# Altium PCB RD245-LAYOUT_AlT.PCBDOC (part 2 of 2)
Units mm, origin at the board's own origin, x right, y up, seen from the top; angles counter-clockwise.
Board outline 75 x 91 mm, 4 copper layers (TOP, Mid-Layer 1, Mid-Layer 2, BOTTOM), stack 0.711 mm thick; 95 components, 67 nets, 327 pads, 801 vias.
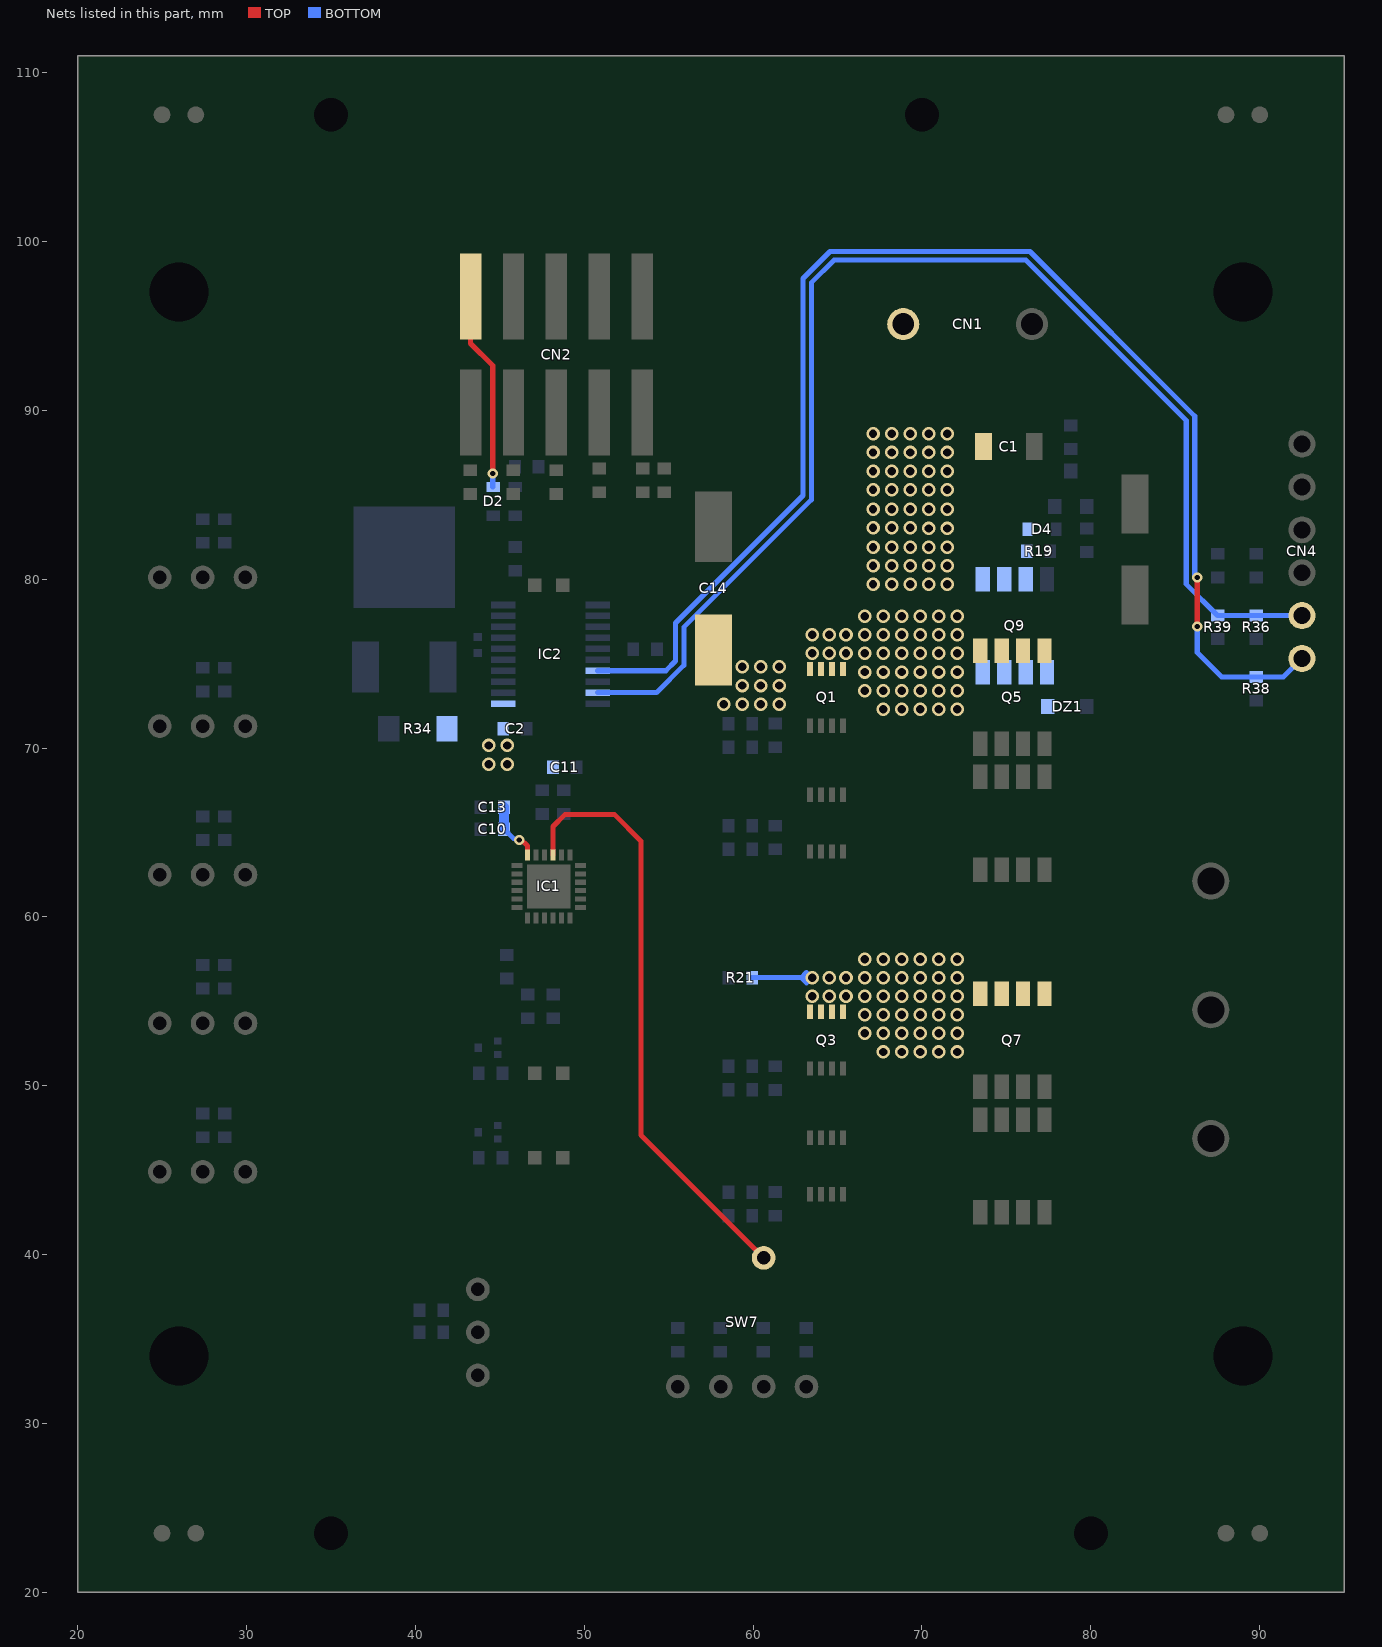
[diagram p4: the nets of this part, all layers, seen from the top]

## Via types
v1: diameter 0.8, hole 0.5, TOP to BOTTOM, 435 vias
v2: diameter 0.6, hole 0.3, TOP to BOTTOM, 356 vias
v3: diameter 0.5, hole 0.25, TOP to BOTTOM, 10 vias

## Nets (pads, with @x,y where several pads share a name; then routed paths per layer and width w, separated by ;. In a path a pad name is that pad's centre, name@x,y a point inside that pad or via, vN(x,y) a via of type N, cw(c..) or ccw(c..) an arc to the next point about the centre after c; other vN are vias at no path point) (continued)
SIG642: CN4.5 IC2.19 R36.1 R39.2 | length 75.6
  BOTTOM w0.3: IC2.19@50.8,73.275 54.275,73.275 55.9,74.9 55.9,77.15 63.45,84.7 63.45,97.55 64.8,98.9 76.15,98.9 85.65,89.4 85.65,79.7 R39.2@87.5,77.85 R36.1@89.8,77.85 89.81,77.84 CN4.5@92.5,77.84
SIG643: CN4.6 IC2.17 R38.2 | length 80
  TOP w0.3: v2(86.3,77.2) v2(86.3,80.1)
  BOTTOM w0.3: IC2.17@50.8,74.575 54.825,74.575 55.4,75.15 55.4,77.4 62.95,84.95 62.95,97.8 64.55,99.4 76.4,99.4 86.15,89.65 86.15,80.4 ; v2@86.15,80.25 86.15,80.4 ; v2(86.3,77.2) 86.3,75.65 87.75,74.2 R38.2@89.8,74.2 91.4,74.2 CN4.6@92.5,75.3 ; v2(86.3,80.1) 86.15,80.4
VB: C2.2 C10.2 C11.2 C13.2 C14.2 DZ1.C IC1.18 IC2.1 Q1.5 Q1.6 Q1.7 Q1.8 Q3.5 Q3.6 Q3.7 Q3.8 Q5.5 Q5.6 Q5.7 Q5.8 Q7.5 Q7.6 Q7.7 Q7.8 Q9.5 Q9.6 Q9.7 Q9.8 R21.1 R34.1 | length 8
  TOP w0.3: v2(46.15,64.55) 46.5,64.35 46.65,64.2 IC1.18@46.65,63.675
  BOTTOM w0.3: C10.2@45.25,65.2 45.8,64.65 v2(46.15,64.55) ; R21.1@59.95,56.4 62.85,56.4 ; 63.15,56.1 62.85,56.4 ; 63.15,56.7 62.85,56.4 ; v1(63.5,56.4) 62.85,56.4
  BOTTOM w0.6: C10.2@45.25,65.2 C13.2@45.25,66.5
  other v1: 67.7,52 68.8,52 69.9,52 71,52 72.1,52 66.6,53.1 67.7,53.1 68.8,53.1 69.9,53.1 71,53.1 72.1,53.1 66.6,54.2 67.7,54.2 68.8,54.2 69.9,54.2 71,54.2 72.1,54.2 63.5,55.3 64.5,55.3 65.5,55.3 66.6,55.3 67.7,55.3 68.8,55.3 69.9,55.3 71,55.3 72.1,55.3 64.5,56.4 65.5,56.4 66.6,56.4 67.7,56.4 68.8,56.4 69.9,56.4 71,56.4 72.1,56.4 66.6,57.5 67.7,57.5 68.8,57.5 69.9,57.5 71,57.5 72.1,57.5 44.35,69.05 45.45,69.05 44.35,70.15 45.45,70.15 67.7,72.3 68.8,72.3 69.9,72.3 71,72.3 72.1,72.3 58.25,72.6 59.35,72.6 60.45,72.6 61.55,72.6 66.6,73.4 67.7,73.4 68.8,73.4 69.9,73.4 71,73.4 72.1,73.4 59.35,73.7 60.45,73.7 61.55,73.7 66.6,74.5 67.7,74.5 68.8,74.5 69.9,74.5 71,74.5 72.1,74.5 59.35,74.8 60.45,74.8 61.55,74.8 63.5,75.6 64.5,75.6 65.5,75.6 66.6,75.6 67.7,75.6 68.8,75.6 69.9,75.6 71,75.6 72.1,75.6 63.5,76.7 64.5,76.7 65.5,76.7 66.6,76.7 67.7,76.7 68.8,76.7 69.9,76.7 71,76.7 72.1,76.7 66.6,77.8 67.7,77.8 68.8,77.8 69.9,77.8 71,77.8 72.1,77.8
VBAT: C1.1 CN1.1 D4.K Q9.1 Q9.2 Q9.3 R19.1
  other v1: 67.1,79.7 68.2,79.7 69.3,79.7 70.4,79.7 71.5,79.7 67.1,80.8 68.2,80.8 69.3,80.8 70.4,80.8 71.5,80.8 67.1,81.9 68.2,81.9 69.3,81.9 70.4,81.9 71.5,81.9 70.4,83 71.5,83 67.1,83.05 68.2,83.05 69.3,83.05 67.1,84.15 68.2,84.15 69.3,84.15 70.4,84.15 71.5,84.15 67.1,85.3 68.2,85.3 69.3,85.3 70.4,85.3 71.5,85.3 67.1,86.4 68.2,86.4 69.3,86.4 70.4,86.4 71.5,86.4 67.1,87.5 68.2,87.5 69.3,87.5 70.4,87.5 71.5,87.5 67.1,88.6 68.2,88.6 69.3,88.6 70.4,88.6 71.5,88.6
VDS: IC1.15 SW7.C | length 35.5
  TOP w0.3: IC1.15@48.15,63.675 48.15,65.35 48.85,66.05 51.8,66.05 53.35,64.5 53.35,47.08 SW7.C@60.62,39.81
VEXT: CN2.2 D2.A | length 11.8
  TOP w0.3: CN2.2@43.27,96.729 43.27,93.96 44.58,92.65 v2(44.58,86.25)
  BOTTOM w0.3: v2(44.58,86.25) 44.58,85.47 D2.A@44.6,85.45
pads on no net: IC2.4 IC2.6 IC2.9 IC2.12 IC2.18

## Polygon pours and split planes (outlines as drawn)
no net on TOP "TOP3" (solid, pour order 52): 21,105 21,110 94,110 94,105
no net on TOP "TOP4" (solid, pour order 53): 21,21 21,26 94,26 94,21
VBAT on TOP "TOP1" (solid, pour order 50): 64.9,79.775 64.9,96.879 cw(c64.95,96.879) 64.915,96.915 65.385,97.385 cw(c65.421,97.35) 65.421,97.4 74.379,97.4 cw(c74.379,97.35) 74.415,97.385 74.885,96.915 cw(c74.85,96.879) 74.9,96.879 74.9,79.775 74.4,79.275 65.4,79.275
VB on TOP "TOP7" (solid, pour order 56): 66.846,71.675 cw(c66.846,71.725) 66.81,71.69 66.25,72.25 62.1,72.25 cw(c62.1,72.3) 62.05,72.3 62.05,78.525 cw(c62.1,78.525) 62.1,78.575 77.159,78.575 cw(c77.159,78.525) 77.195,78.56 77.665,78.09 cw(c77.63,78.054) 77.68,78.054 77.68,71.725 cw(c77.63,71.725) 77.63,71.675
GND on TOP "TOP8" (solid, pour order 57): 63.646,58.55 cw(c63.646,58.6) 63.61,58.565 63.115,59.06 cw(c63.15,59.096) 63.1,59.096 63.1,64.25 cw(c63.15,64.25) 63.15,64.3 64.875,64.3 cw(c64.875,64.25) 64.925,64.25 64.925,63.55 ccw(c65.225,63.55) 65.225,63.25 66.425,63.25 66.685,63.51 cw(c66.721,63.475) 66.721,63.525 67.209,63.525 67.21,63.525 76.36,63.525 cw(c76.36,63.475) 76.41,63.475 76.41,59.071 cw(c76.36,59.071) 76.395,59.035 75.925,58.565 cw(c75.889,58.6) 75.889,58.55
VB on TOP "TOP9" (solid, pour order 58): 66.771,51.375 cw(c66.771,51.425) 66.735,51.39 66.175,51.95 62.1,51.95 cw(c62.1,52) 62.05,52 62.05,58 cw(c62.1,58) 62.1,58.05 77.159,58.05 cw(c77.159,58) 77.195,58.035 77.665,57.565 cw(c77.63,57.529) 77.68,57.529 77.68,51.425 cw(c77.63,51.425) 77.63,51.375
OUT1 on TOP "TOP11" (solid, pour order 60): 79.321,58.55 cw(c79.321,58.6) 79.285,58.565 78.815,59.035 cw(c78.85,59.071) 78.8,59.071 78.8,63.1 77.675,64.225 66.796,64.225 cw(c66.796,64.275) 66.76,64.24 66.2,64.8 63.1,64.8 cw(c63.1,64.85) 63.05,64.85 63.05,71.7 cw(c63.1,71.7) 63.1,71.75 64.875,71.75 cw(c64.875,71.7) 64.925,71.7 64.925,71 ccw(c65.225,71) 65.225,70.7 66.4,70.7 66.66,70.96 cw(c66.696,70.925) 66.696,70.975 76.36,70.975 cw(c76.36,70.925) 76.41,70.925 76.41,69.525 ccw(c76.71,69.525) 76.71,69.225 77.655,69.225 ccw(c77.655,69.55) 77.98,69.55 77.98,69.6 cw(c78.03,69.6) 78.03,69.65 78.2,69.65 ccw(c78.2,70.25) 78.8,70.25 78.8,70.779 cw(c78.85,70.779) 78.815,70.815 78.985,70.985 cw(c79.021,70.95) 79.021,71 80.329,71 cw(c80.329,70.95) 80.365,70.985 86,65.35 90.479,65.35 cw(c90.479,65.3) 90.515,65.335 90.985,64.865 cw(c90.95,64.829) 91,64.829 91,59.071 cw(c90.95,59.071) 90.985,59.035 90.515,58.565 cw(c90.479,58.6) 90.479,58.55
OUT2 on TOP "TOP12" (solid, pour order 61): 79.601,43.925 66.796,43.925 cw(c66.796,43.975) 66.76,43.94 66.2,44.5 63.1,44.5 cw(c63.1,44.55) 63.05,44.55 63.05,51.4 cw(c63.1,51.4) 63.1,51.45 64.875,51.45 cw(c64.875,51.4) 64.925,51.4 64.925,50.7 ccw(c65.225,50.7) 65.225,50.4 66.35,50.4 66.61,50.66 cw(c66.646,50.625) 66.646,50.675 76.36,50.675 cw(c76.36,50.625) 76.41,50.625 76.41,49.225 ccw(c76.71,49.225) 76.71,48.925 77.655,48.925 ccw(c77.655,49.25) 77.98,49.25 77.98,49.259 cw(c78.03,49.259) 77.995,49.295 78.035,49.335 cw(c78.071,49.3) 78.071,49.35 78.2,49.35 ccw(c78.2,49.95) 78.8,49.95 78.8,57.529 cw(c78.85,57.529) 78.815,57.565 79.285,58.035 cw(c79.321,58) 79.321,58.05 90.479,58.05 cw(c90.479,58) 90.515,58.035 90.985,57.565 cw(c90.95,57.529) 91,57.529 91,51.771 cw(c90.95,51.771) 90.985,51.735 90.515,51.265 cw(c90.479,51.3) 90.479,51.25 86.85,51.25 85.4,49.8 85.4,46.671 cw(c85.35,46.671) 85.385,46.635 82.69,43.94 cw(c82.654,43.975) 82.654,43.925
N622087 on TOP "TOP5" (solid, pour order 54): 81.85,84.8 cw(c81.85,84.85) 81.8,84.85 81.8,86.35 81.676,86.474 81.615,86.535 cw(c81.65,86.571) 81.6,86.571 81.6,87.929 cw(c81.65,87.929) 81.615,87.965 81.835,88.185 81.836,88.186 82.835,89.185 cw(c82.871,89.15) 82.871,89.2 93.029,89.2 cw(c93.029,89.15) 93.065,89.185 93.285,88.965 cw(c93.25,88.929) 93.3,88.929 93.3,87.471 cw(c93.25,87.471) 93.285,87.435 93.065,87.215 cw(c93.029,87.25) 93.029,87.2 84.25,87.2 83.586,86.536 83.585,86.535 83.4,86.35 83.4,84.85 cw(c83.35,84.85) 83.35,84.8
GND on TOP "TOP2" (solid, pour order 51): 43.571,57.6 cw(c43.571,57.65) 43.535,57.615 39.765,61.385 cw(c39.8,61.421) 39.75,61.421 39.75,61.629 cw(c39.8,61.629) 39.765,61.665 39.935,61.835 cw(c39.971,61.8) 39.971,61.85 40.184,61.85 cw(c40.184,61.8) 40.22,61.835 41.34,60.715 cw(c41.304,60.68) 41.351,60.697 41.43,60.48 41.43,60.479 41.43,60.478 ccw(c41.9,60.65) 41.9,60.15 42.834,60.15 cw(c42.834,60.1) 42.87,60.135 43.503,59.503 ccw(c43.75,59.75) 43.75,59.4 43.76,59.4 cw(c43.76,59.35) 43.781,59.395 43.985,59.299 43.985,59.298 ccw(c44.2,59.75) 44.531,59.375 44.83,59.636 44.833,59.639 45.283,60.038 ccw(c45.05,60.3) 45.297,60.052 45.298,60.053 45.299,60.054 45.43,60.185 cw(c45.466,60.15) 45.443,60.195 cw(c45.466,60.15) 45.466,60.2 46.079,60.2 cw(c46.079,60.15) 46.115,60.185 46.285,60.015 cw(c46.25,59.979) 46.3,59.979 46.3,59.607 cw(c46.25,59.607) 46.262,59.558 cw(c46.25,59.607) 46.257,59.557 46.179,59.545 46.178,59.545 ccw(c46.25,59.05) 46.256,58.55 46.257,58.55 46.279,58.55 cw(c46.279,58.5) 46.315,58.535 46.485,58.365 cw(c46.45,58.329) 46.5,58.329 46.5,57.771 cw(c46.45,57.771) 46.485,57.735 46.365,57.615 cw(c46.329,57.65) 46.352,57.605 cw(c46.329,57.65) 46.329,57.6
GND on TOP "TOP6" (solid, pour order 55): 43.566,60.45 cw(c43.566,60.5) 43.543,60.455 cw(c43.566,60.5) 43.53,60.465 39.765,64.23 cw(c39.8,64.266) 39.75,64.266 39.75,72.534 cw(c39.8,72.534) 39.765,72.57 43.48,76.285 cw(c43.516,76.25) 43.493,76.295 cw(c43.516,76.25) 43.516,76.3 49.2,76.3 ccw(c49.2,76.65) 49.447,76.403 51.047,78.003 ccw(c50.8,78.25) 51.15,78.25 51.15,82.334 cw(c51.2,82.334) 51.165,82.37 52.13,83.335 cw(c52.166,83.3) 52.166,83.35 52.479,83.35 cw(c52.479,83.3) 52.515,83.335 52.585,83.265 cw(c52.55,83.229) 52.6,83.229 52.6,72.166 cw(c52.55,72.166) 52.585,72.13 46.615,66.16 cw(c46.58,66.196) 46.596,66.149 46.38,66.07 46.376,66.069 ccw(c46.55,65.6) 46.05,65.6 46.05,65.079 cw(c46,65.079) 46.044,65.055 cw(c46,65.079) 46.014,65.031 ccw(c46.15,64.55) 45.65,64.55 ccw(c46.15,64.55) 46.078,64.055 46.079,64.055 46.081,64.055 46.257,64.03 cw(c46.25,63.981) 46.3,63.981 46.3,63.621 cw(c46.25,63.621) 46.297,63.603 cw(c46.25,63.621) 46.285,63.585 46.115,63.415 cw(c46.079,63.45) 46.093,63.402 cw(c46.079,63.45) 46.079,63.4 45.466,63.4 cw(c45.466,63.45) 45.45,63.403 cw(c45.466,63.45) 45.43,63.415 45.061,63.784 cw(c45.096,63.82) 45.049,63.803 44.97,64.02 44.97,64.021 44.969,64.024 44.968,64.025 ccw(c44.5,63.85) 44.325,63.381 44.327,63.381 44.329,63.38 44.33,63.38 44.331,63.38 44.331,63.379 44.547,63.301 cw(c44.53,63.254) 44.566,63.29 44.566,63.289 45.052,62.803 45.053,62.802 ccw(c45.3,63.05) 45.3,62.7 45.85,62.7 cw(c45.85,62.65) 45.9,62.65 45.9,62.45 cw(c45.85,62.45) 45.85,62.4 45.033,62.4 cw(c45.033,62.45) 45.003,62.41 44.983,62.425 cw(c45.012,62.466) 44.968,62.443 44.846,62.676 44.845,62.678 ccw(c44.4,62.45) 43.9,62.444 43.9,62.443 43.9,60.5 cw(c43.85,60.5) 43.85,60.45
VB on TOP "TOP10" (solid, pour order 59): 59.321,51.95 cw(c59.321,52) 59.285,51.965 55.265,55.985 cw(c55.3,56.021) 55.25,56.021 55.25,76.779 cw(c55.3,76.779) 55.265,76.815 57.01,78.56 cw(c57.046,78.525) 57.046,78.575 63.45,78.575 cw(c63.45,78.525) 63.5,78.525 63.5,72.3 cw(c63.45,72.3) 63.45,72.25 62.5,72.25 61.95,71.7 61.95,66.245 cw(c61.9,66.245) 61.918,66.199 61.917,66.198 ccw(c62.2,65.45) 61.918,64.701 cw(c61.9,64.655) 61.95,64.655 61.95,58.75 62.65,58.05 63.3,58.05 cw(c63.3,58) 63.35,58 63.35,52 cw(c63.3,52) 63.3,51.95
GND on TOP "TOP13" (solid, pour order 62): 39.671,74.45 cw(c39.671,74.5) 39.635,74.465 39.565,74.535 cw(c39.6,74.571) 39.55,74.571 39.55,75.434 cw(c39.6,75.434) 39.565,75.47 44.48,80.385 cw(c44.516,80.35) 44.516,80.4 46.65,80.4 ccw(c46.65,80.75) 46.897,80.503 49.48,83.085 cw(c49.516,83.05) 49.516,83.1 49.85,83.1 49.95,83 49.95,78.666 cw(c49.9,78.666) 49.935,78.63 48.82,77.515 cw(c48.784,77.55) 48.807,77.505 cw(c48.784,77.55) 48.784,77.5 43.05,77.5 ccw(c43.05,77.15) 42.803,77.397 42.554,77.149 42.553,77.148 39.87,74.465 cw(c39.834,74.5) 39.834,74.45
GND on TOP "TOP14" (solid, pour order 63): 31.521,29 cw(c31.521,29.05) 31.498,29.005 cw(c31.521,29.05) 31.485,29.015 31.015,29.485 cw(c31.05,29.521) 31.002,29.507 cw(c31.05,29.521) 31,29.521 31,34 ccw(c26,34) 26,39 21.521,39 cw(c21.521,39.05) 21.498,39.005 cw(c21.521,39.05) 21.485,39.015 21.015,39.485 cw(c21.05,39.521) 21.002,39.507 cw(c21.05,39.521) 21,39.521 21,91.479 cw(c21.05,91.479) 21.001,91.491 cw(c21.05,91.479) 21.015,91.515 21.016,91.516 21.485,91.985 cw(c21.521,91.95) 21.507,91.998 cw(c21.521,91.95) 21.521,92 26,92 ccw(c26,97) 31,97 31,101.479 cw(c31.05,101.479) 31.001,101.491 cw(c31.05,101.479) 31.015,101.515 31.016,101.516 31.485,101.985 cw(c31.521,101.95) 31.507,101.998 cw(c31.521,101.95) 31.521,102 83.479,102 cw(c83.479,101.95) 83.502,101.995 cw(c83.479,101.95) 83.515,101.985 83.517,101.983 83.518,101.982 83.984,101.516 83.985,101.515 cw(c83.95,101.479) 84,101.479 84,97 ccw(c89,97) 89,92 93.479,92 cw(c93.479,91.95) 93.502,91.995 cw(c93.479,91.95) 93.515,91.985 93.517,91.983 93.518,91.982 93.984,91.516 93.985,91.515 cw(c93.95,91.479) 94,91.479 94,39.521 cw(c93.95,39.521) 93.999,39.508 cw(c93.95,39.521) 93.985,39.485 93.984,39.484 93.515,39.015 cw(c93.479,39.05) 93.493,39.002 cw(c93.479,39.05) 93.479,39 89.051,39 89.05,39 ccw(c89,34) 84,34 84,29.521 cw(c83.95,29.521) 83.998,29.509 cw(c83.95,29.521) 83.985,29.485 83.984,29.484 83.515,29.015 cw(c83.479,29.05) 83.493,29.002 cw(c83.479,29.05) 83.479,29
GND on Mid-Layer 1 "MID122" (solid, pour order 49): 22,29 cw(c22,30) 21,30 21,101 cw(c22,101) 22,102 93,102 cw(c93,101) 94,101 94,30 cw(c93,30) 93,29
no net on Mid-Layer 1 "MID117" (solid, pour order 44): 21,105 21,110 94,110 94,105
no net on Mid-Layer 1 "MID118" (solid, pour order 45): 21,21 21,26 94,26 94,21
VB on Mid-Layer 1 "MID115" (solid, pour order 42): 66.771,51.375 cw(c66.771,51.425) 66.735,51.39 66.125,52 62.1,52 cw(c62.1,52.05) 62.05,52.05 62.05,58 cw(c62.1,58) 62.1,58.05 72.229,58.05 cw(c72.229,58) 72.265,58.035 72.735,57.565 cw(c72.7,57.529) 72.748,57.543 cw(c72.7,57.529) 72.75,57.529 72.75,51.896 cw(c72.7,51.896) 72.735,51.86 72.265,51.39 cw(c72.229,51.425) 72.243,51.377 cw(c72.229,51.425) 72.229,51.375
VB on Mid-Layer 1 "MID116" (solid, pour order 43): 66.771,71.675 cw(c66.771,71.725) 66.735,71.69 66.125,72.3 62.1,72.3 cw(c62.1,72.35) 62.05,72.35 62.05,78.525 cw(c62.1,78.525) 62.1,78.575 72.25,78.575 72.75,78.075 72.75,72.196 cw(c72.7,72.196) 72.735,72.16 72.265,71.69 cw(c72.229,71.725) 72.243,71.677 cw(c72.229,71.725) 72.229,71.675
VB on Mid-Layer 1 "MID119" (solid, pour order 46): 59.271,52 cw(c59.271,52.05) 59.235,52.015 55.265,55.985 cw(c55.3,56.021) 55.25,56.021 55.25,75.729 cw(c55.3,75.729) 55.265,75.765 58.06,78.56 cw(c58.096,78.525) 58.096,78.575 63.45,78.575 cw(c63.45,78.525) 63.5,78.525 63.5,72.35 cw(c63.45,72.35) 63.45,72.3 62.55,72.3 61.95,71.7 61.95,66.352 cw(c61.9,66.352) 61.935,66.317 61.634,66.016 ccw(c62.2,65.45) 61.634,64.884 61.935,64.583 cw(c61.9,64.548) 61.95,64.548 61.95,58.75 62.65,58.05 63.3,58.05 cw(c63.3,58) 63.35,58 63.35,52.05 cw(c63.3,52.05) 63.3,52
N622087 on Mid-Layer 1 "MID120" (solid, pour order 47): 81.6,86.45 81.6,87.95 81.85,88.2 83.35,88.2 83.6,87.95 83.6,86.45 83.35,86.2 81.85,86.2
N622087 on Mid-Layer 1 "MID121" (solid, pour order 48): 58.8,88.2 58.8,89.7 59.05,89.95 60.55,89.95 60.8,89.7 60.8,88.2 60.55,87.95 59.05,87.95
GND on Mid-Layer 2 "MID233" (solid, pour order 41): 22,29 cw(c22,30) 21,30 21,101 cw(c22,101) 22,102 93,102 cw(c93,101) 94,101 94,30 cw(c93,30) 93,29
no net on Mid-Layer 2 "MID226" (solid, pour order 34): 21,105 21,110 94,110 94,105
no net on Mid-Layer 2 "MID227" (solid, pour order 35): 21,21 21,26 94,26 94,21
VB on Mid-Layer 2 "MID223" (solid, pour order 31): 66.771,51.375 cw(c66.771,51.425) 66.735,51.39 66.125,52 62.1,52 cw(c62.1,52.05) 62.05,52.05 62.05,58 cw(c62.1,58) 62.1,58.05 72.229,58.05 cw(c72.229,58) 72.265,58.035 72.735,57.565 cw(c72.7,57.529) 72.748,57.543 cw(c72.7,57.529) 72.75,57.529 72.75,51.896 cw(c72.7,51.896) 72.735,51.86 72.265,51.39 cw(c72.229,51.425) 72.243,51.377 cw(c72.229,51.425) 72.229,51.375
VB on Mid-Layer 2 "MID224" (solid, pour order 32): 66.771,71.675 cw(c66.771,71.725) 66.735,71.69 66.125,72.3 62.1,72.3 cw(c62.1,72.35) 62.05,72.35 62.05,78.525 cw(c62.1,78.525) 62.1,78.575 72.25,78.575 72.75,78.075 72.75,72.196 cw(c72.7,72.196) 72.735,72.16 72.265,71.69 cw(c72.229,71.725) 72.243,71.677 cw(c72.229,71.725) 72.229,71.675
VBAT on Mid-Layer 2 "MID225" (solid, pour order 33): 64.9,79.775 64.9,96.879 cw(c64.95,96.879) 64.915,96.915 65.385,97.385 cw(c65.421,97.35) 65.421,97.4 74.379,97.4 cw(c74.379,97.35) 74.415,97.385 74.885,96.915 cw(c74.85,96.879) 74.9,96.879 74.9,79.775 74.4,79.275 65.4,79.275
VB on Mid-Layer 2 "MID228" (solid, pour order 36): 59.271,52 cw(c59.271,52.05) 59.235,52.015 55.265,55.985 cw(c55.3,56.021) 55.25,56.021 55.25,75.729 cw(c55.3,75.729) 55.265,75.765 58.06,78.56 cw(c58.096,78.525) 58.096,78.575 63.45,78.575 cw(c63.45,78.525) 63.5,78.525 63.5,72.35 cw(c63.45,72.35) 63.45,72.3 62.55,72.3 61.95,71.7 61.95,66.245 cw(c61.9,66.245) 61.918,66.199 ccw(c62.2,65.45) 61.918,64.701 cw(c61.9,64.655) 61.95,64.655 61.95,58.75 62.65,58.05 63.3,58.05 cw(c63.3,58) 63.35,58 63.35,52.05 cw(c63.3,52.05) 63.3,52
VB on Mid-Layer 2 "MID229" (solid, pour order 37): 55.521,67.85 cw(c55.521,67.9) 55.485,67.865 54.75,68.6 44.171,68.6 cw(c44.171,68.65) 44.135,68.615 43.915,68.835 cw(c43.95,68.871) 43.9,68.871 43.9,70.329 cw(c43.95,70.329) 43.915,70.365 44.135,70.585 cw(c44.171,70.55) 44.171,70.6 54.75,70.6 55.385,71.235 cw(c55.421,71.2) 55.421,71.25 55.85,71.25 cw(c55.85,71.2) 55.9,71.2 55.9,67.9 cw(c55.85,67.9) 55.85,67.85
OUT2 on Mid-Layer 2 "MID230" (solid, pour order 38): 79.601,43.925 66.796,43.925 cw(c66.796,43.975) 66.76,43.94 66.15,44.55 63.546,44.55 cw(c63.546,44.6) 63.51,44.565 63.04,45.035 cw(c63.075,45.071) 63.025,45.071 63.025,50.179 cw(c63.075,50.179) 63.04,50.215 63.51,50.685 cw(c63.546,50.65) 63.546,50.7 65.663,50.7 ccw(c66.15,51.05) 66.618,50.675 72.75,50.675 73.25,51.175 73.25,57.55 73.75,58.05 90.5,58.05 91,57.55 91,51.771 cw(c90.95,51.771) 90.985,51.735 90.515,51.265 cw(c90.479,51.3) 90.479,51.25 86.85,51.25 85.4,49.8 85.4,46.671 cw(c85.35,46.671) 85.385,46.635 82.69,43.94 cw(c82.654,43.975) 82.654,43.925
GND on Mid-Layer 2 "MID231" (solid, pour order 39): 63.625,58.55 63.125,59.05 63.125,63.025 63.625,63.525 65.682,63.525 ccw(c66.15,63.9) 66.618,63.525 75.91,63.525 76.41,63.025 76.41,59.05 75.91,58.55
OUT1 on Mid-Layer 2 "MID232" (solid, pour order 40): 77.431,58.55 cw(c77.431,58.6) 77.395,58.565 76.925,59.035 cw(c76.96,59.071) 76.91,59.071 76.91,63.725 76.41,64.225 66.796,64.225 cw(c66.796,64.275) 66.76,64.24 66.15,64.85 63.546,64.85 cw(c63.546,64.9) 63.51,64.865 63.04,65.335 cw(c63.075,65.371) 63.025,65.371 63.025,70.454 cw(c63.075,70.454) 63.04,70.49 63.51,70.96 cw(c63.546,70.925) 63.546,70.975 65.732,70.975 ccw(c66.2,71.35) 66.668,70.975 80.354,70.975 cw(c80.354,70.925) 80.39,70.96 86,65.35 90.5,65.35 91,64.85 91,59.071 cw(c90.95,59.071) 90.985,59.035 90.515,58.565 cw(c90.479,58.6) 90.479,58.55
GND on BOTTOM "BOTTOM62" (solid, pour order 30): 50.121,65 cw(c50.121,65.05) 50.085,65.015 49.915,65.185 cw(c49.95,65.221) 49.902,65.207 cw(c49.95,65.221) 49.9,65.221 49.9,68.21 cw(c49.95,68.21) 49.901,68.22 cw(c49.95,68.21) 49.92,68.25 cw(c49.95,68.21) 49.936,68.259 ccw(c49.875,68.475) 50.048,68.331 cw(c50.087,68.3) 50.059,68.342 cw(c50.087,68.3) 50.075,68.348 cw(c50.087,68.3) 50.087,68.35 52.05,68.35 ccw(c52.05,68.85) 52.404,68.496 57.504,73.596 ccw(c57.15,73.95) 57.65,73.95 57.65,76.372 cw(c57.7,76.372) 57.665,76.408 65.254,83.996 ccw(c64.9,84.35) 65.4,84.35 65.4,89.172 cw(c65.45,89.172) 65.401,89.184 cw(c65.45,89.172) 65.415,89.208 65.416,89.209 66.692,90.485 cw(c66.728,90.45) 66.714,90.498 cw(c66.728,90.45) 66.728,90.5 76.672,90.5 cw(c76.672,90.45) 76.695,90.495 cw(c76.672,90.45) 76.708,90.485 78.185,89.008 cw(c78.15,88.972) 78.2,88.972 78.2,85.975 ccw(c78.425,85.975) 78.425,85.75 79.175,85.75 ccw(c79.175,85.975) 79.4,85.975 79.4,86 cw(c79.45,86) 79.45,86.05 79.884,86.05 cw(c79.884,86) 79.907,86.045 cw(c79.884,86) 79.92,86.035 80.634,85.321 80.635,85.32 cw(c80.6,85.284) 80.65,85.284 80.65,80.716 cw(c80.6,80.716) 80.649,80.704 cw(c80.6,80.716) 80.635,80.68 80.634,80.679 80.32,80.365 cw(c80.284,80.4) 80.298,80.352 cw(c80.284,80.4) 80.284,80.35 78.351,80.35 cw(c78.351,80.4) 78.315,80.365 78.145,80.535 cw(c78.18,80.571) 78.132,80.557 cw(c78.18,80.571) 78.13,80.571 78.13,81 cw(c78.18,81) 78.135,81.022 cw(c78.18,81) 78.147,81.037 ccw(c77.925,81.275) 78.25,81.275 78.25,82.025 78.25,82.208 cw(c78.3,82.208) 78.288,82.256 78.29,82.257 ccw(c78.225,82.575) 78.55,82.575 78.55,84.725 ccw(c78.225,84.725) 78.225,85.05 77.271,85.05 cw(c77.271,85.1) 77.235,85.065 77.065,85.235 cw(c77.1,85.271) 77.052,85.257 cw(c77.1,85.271) 77.05,85.271 77.05,88.579 ccw(c76.5,88.579) 76.889,88.968 76.418,89.439 ccw(c76.029,89.05) 76.029,89.6 67.021,89.6 ccw(c67.021,89.05) 66.632,89.439 66.161,88.968 ccw(c66.55,88.579) 66,88.579 66,79.621 cw(c65.95,79.621) 65.999,79.609 cw(c65.95,79.621) 65.985,79.585 65.984,79.584 65.516,79.116 65.515,79.115 cw(c65.479,79.15) 65.479,79.1 61.021,79.1 ccw(c61.021,78.85) 60.844,79.027 60.843,79.026 60.82,79.003 60.819,79.002 cw(c60.784,79.038) 60.809,78.995 ccw(c61.096,78.525) 60.707,78.914 58.211,76.418 ccw(c58.6,76.029) 58.13,76.315 cw(c58.087,76.341) 58.123,76.306 ccw(c58.3,76.129) 58.05,76.129 58.05,73.778 cw(c58,73.778) 58.035,73.742 57.511,73.218 ccw(c57.9,72.829) 57.35,72.829 57.35,71.921 cw(c57.3,71.921) 57.335,71.885 57.265,71.815 cw(c57.229,71.85) 57.229,71.8 57.2,71.8 ccw(c57.2,71.45) 56.952,71.697 50.27,65.015 cw(c50.234,65.05) 50.248,65.002 cw(c50.234,65.05) 50.234,65
GND on BOTTOM "BOTTOM61" (solid, pour order 29): 31.521,29 cw(c31.521,29.05) 31.498,29.005 cw(c31.521,29.05) 31.485,29.015 31.015,29.485 cw(c31.05,29.521) 31.002,29.507 cw(c31.05,29.521) 31,29.521 31,34 ccw(c26,34) 26,39 21.521,39 cw(c21.521,39.05) 21.498,39.005 cw(c21.521,39.05) 21.485,39.015 21.015,39.485 cw(c21.05,39.521) 21.002,39.507 cw(c21.05,39.521) 21,39.521 21,91.479 cw(c21.05,91.479) 21.001,91.491 cw(c21.05,91.479) 21.015,91.515 21.016,91.516 21.485,91.985 cw(c21.521,91.95) 21.507,91.998 cw(c21.521,91.95) 21.521,92 26,92 ccw(c26,97) 31,97 31,101.479 cw(c31.05,101.479) 31.001,101.491 cw(c31.05,101.479) 31.015,101.515 31.016,101.516 31.485,101.985 cw(c31.521,101.95) 31.507,101.998 cw(c31.521,101.95) 31.521,102 83.478,102 cw(c83.478,101.95) 83.5,101.995 cw(c83.478,101.95) 83.508,101.99 83.513,101.986 cw(c83.483,101.946) 83.518,101.982 83.519,101.981 83.984,101.516 83.985,101.515 cw(c83.95,101.479) 83.998,101.491 cw(c83.95,101.479) 84,101.479 84,97 ccw(c89,97) 89,92 93.478,92 cw(c93.478,91.95) 93.5,91.995 cw(c93.478,91.95) 93.508,91.99 93.513,91.986 cw(c93.483,91.946) 93.518,91.982 93.519,91.981 93.984,91.516 93.985,91.515 cw(c93.95,91.479) 93.999,91.491 cw(c93.95,91.479) 94,91.479 94,39.52 cw(c93.95,39.52) 93.999,39.508 cw(c93.95,39.52) 93.985,39.484 93.984,39.483 93.515,39.014 cw(c93.479,39.049) 93.493,39.001 cw(c93.479,39.049) 93.479,38.999 89.1,38.999 89.099,38.999 ccw(c89,34) 84,34 84,29.521 cw(c83.95,29.521) 83.998,29.509 cw(c83.95,29.521) 83.985,29.485 83.984,29.484 83.515,29.015 cw(c83.479,29.05) 83.493,29.002 cw(c83.479,29.05) 83.479,29
no net on BOTTOM "BOTTOM44" (solid, pour order 12): 21,21 21,26 94,26 94,21
no net on BOTTOM "BOTTOM45" (solid, pour order 13): 21,105 21,110 94,110 94,105
GND on BOTTOM "BOTTOM34" (solid, pour order 2): 46.65,60.5 cw(c46.65,60.55) 46.6,60.55 46.6,63.05 cw(c46.65,63.05) 46.65,63.1 49.15,63.1 cw(c49.15,63.05) 49.2,63.05 49.2,60.55 cw(c49.15,60.55) 49.15,60.5
GND on BOTTOM "BOTTOM40" (solid, pour order 8): 51.79,64.25 cw(c51.79,64.3) 51.769,64.255 51.679,64.298 cw(c51.7,64.343) 51.65,64.343 51.65,64.634 cw(c51.7,64.634) 51.665,64.67 56.68,69.685 cw(c56.716,69.65) 56.716,69.7 57.951,69.7 cw(c57.951,69.65) 57.993,69.678 cw(c57.951,69.65) 58.001,69.655 ccw(c58.225,69.675) 58.225,69.45 60.275,69.45 ccw(c60.275,69.675) 60.404,69.491 cw(c60.433,69.45) 60.433,69.5 62.325,69.5 62.525,69.3 62.525,65.25 62.325,65.05 62.1,65.05 61.9,65.25 61.9,65.725 ccw(c61.675,65.725) 61.675,65.95 60.925,65.95 ccw(c60.925,65.725) 60.7,65.725 60.7,65.3 cw(c60.65,65.3) 60.65,65.25 60.55,65.25 cw(c60.55,65.3) 60.5,65.3 60.5,65.775 ccw(c60.275,65.775) 60.275,66 58.225,66 ccw(c58.225,65.775) 58,65.775 58,65.366 cw(c57.95,65.366) 57.999,65.354 cw(c57.95,65.366) 57.985,65.33 57.984,65.329 56.92,64.265 cw(c56.884,64.3) 56.898,64.252 cw(c56.884,64.3) 56.884,64.25
GND on BOTTOM "BOTTOM41" (solid, pour order 9): 60.583,51.7 cw(c60.583,51.75) 60.561,51.705 cw(c60.583,51.75) 60.554,51.71 ccw(c60.425,51.525) 60.425,51.75 58.467,51.75 58.466,51.75 cw(c58.466,51.8) 58.438,51.758 cw(c58.466,51.8) 58.424,51.772 57.565,52.63 cw(c57.6,52.666) 57.55,52.666 57.55,53.6 ccw(c57.2,53.6) 57.448,53.847 57.447,53.848 51.661,59.634 cw(c51.696,59.67) 51.649,59.653 51.603,59.78 cw(c51.65,59.797) 51.6,59.8 51.6,60.107 cw(c51.65,60.107) 51.629,60.152 51.718,60.195 cw(c51.74,60.15) 51.74,60.2 54.234,60.2 cw(c54.234,60.15) 54.27,60.185 57.985,56.47 cw(c57.95,56.434) 58,56.434 58,56.025 ccw(c58.225,56.025) 58.225,55.8 60.275,55.8 ccw(c60.275,56.025) 60.499,56.005 cw(c60.549,56) 60.507,56.028 cw(c60.549,56) 60.549,56.05 62.3,56.05 62.5,55.85 62.5,51.9 62.3,51.7
VB on BOTTOM "BOTTOM43" (solid, pour order 11): 66.606,51.55 66.538,51.608 ccw(c66.247,51.264) 66.475,51.652 cw(c66.5,51.696) 66.465,51.66 66.125,52 63.5,52 63,52.5 63,57.55 63.5,58.05 72.229,58.05 cw(c72.229,58) 72.252,58.045 cw(c72.229,58) 72.265,58.035 72.735,57.565 cw(c72.7,57.529) 72.748,57.543 cw(c72.7,57.529) 72.75,57.529 72.75,51.896 cw(c72.7,51.896) 72.745,51.873 cw(c72.7,51.896) 72.735,51.86 72.425,51.55
GND on BOTTOM "BOTTOM46" (solid, pour order 14): 41.8,36.05 cw(c41.75,36.05) 41.75,36 41.55,36 cw(c41.55,36.05) 41.5,36.05 41.5,36.7 cw(c41.55,36.7) 41.55,36.75 41.75,36.75 cw(c41.75,36.7) 41.8,36.7
GND on BOTTOM "BOTTOM48" (solid, pour order 16): 45.95,65.85 45.776,66.024 ccw(c45.575,66.125) 45.8,66.125 45.8,66.875 ccw(c45.575,66.875) 45.75,67.016 45.75,68.017 46.083,68.35 46.679,68.35 cw(c46.679,68.3) 46.715,68.335 46.885,68.165 cw(c46.85,68.129) 46.9,68.129 46.9,66.3 46.7,66.1 46.55,66.1 ccw(c46.55,65.6) 46.131,65.873 cw(c46.089,65.9) 46.089,65.85
OUT2 on BOTTOM "BOTTOM55" (solid, pour order 23): 77.481,43.925 cw(c77.481,43.975) 77.453,43.933 cw(c77.481,43.975) 77.448,43.938 ccw(c77.15,43.6) 77.305,44.022 cw(c77.322,44.069) 77.295,44.027 ccw(c77.05,43.65) 77.05,44.1 66.649,44.1 cw(c66.649,44.15) 66.622,44.108 66.539,44.162 cw(c66.567,44.204) 66.531,44.169 66.15,44.55 63.546,44.55 cw(c63.546,44.6) 63.523,44.555 cw(c63.546,44.6) 63.51,44.565 63.04,45.035 cw(c63.075,45.071) 63.027,45.057 cw(c63.075,45.071) 63.025,45.071 63.025,50.154 cw(c63.075,50.154) 63.026,50.166 cw(c63.075,50.154) 63.04,50.19 63.041,50.191 63.535,50.685 cw(c63.571,50.65) 63.571,50.7 65.663,50.7 ccw(c66.15,51.05) 66.597,50.65 76.843,50.65 cw(c76.843,50.6) 76.878,50.635 76.879,50.635 77.553,49.961 cw(c77.518,49.925) 77.565,49.941 77.636,49.746 77.636,49.744 ccw(c78.2,49.95) 78.8,49.95 78.8,57.55 79.3,58.05 90.479,58.05 cw(c90.479,58) 90.515,58.035 90.985,57.565 cw(c90.95,57.529) 91,57.529 91,51.771 cw(c90.95,51.771) 90.999,51.759 cw(c90.95,51.771) 90.985,51.735 90.984,51.734 90.515,51.265 cw(c90.479,51.3) 90.479,51.25 86.85,51.25 85.4,49.8 85.4,46.671 cw(c85.35,46.671) 85.399,46.659 cw(c85.35,46.671) 85.385,46.635 85.384,46.634 82.69,43.94 cw(c82.654,43.975) 82.654,43.925
GND on BOTTOM "BOTTOM56" (solid, pour order 24): 60.549,56.75 cw(c60.549,56.8) 60.499,56.796 ccw(c60.275,56.775) 60.275,57 58.466,57 cw(c58.466,57.05) 58.452,57.002 cw(c58.466,57.05) 58.43,57.015 54.647,60.797 ccw(c54.4,60.55) 54.4,60.9 52.021,60.9 cw(c52.021,60.95) 52.007,60.902 cw(c52.021,60.95) 51.985,60.915 51.815,61.085 cw(c51.85,61.121) 51.802,61.107 cw(c51.85,61.121) 51.8,61.121 51.8,62.479 cw(c51.85,62.479) 51.815,62.515 51.816,62.516 51.985,62.685 cw(c52.021,62.65) 52.007,62.698 cw(c52.021,62.65) 52.021,62.7 57.6,62.7 ccw(c57.6,63.05) 57.847,62.803 58.43,63.385 cw(c58.466,63.35) 58.452,63.398 cw(c58.466,63.35) 58.466,63.4 60.425,63.4 ccw(c60.425,63.625) 60.554,63.441 cw(c60.583,63.4) 60.583,63.45 61.825,63.45 ccw(c61.825,63.675) 61.999,63.532 cw(c62.037,63.5) 62.015,63.545 cw(c62.037,63.5) 62.024,63.548 cw(c62.037,63.5) 62.037,63.55 65.663,63.55 ccw(c66.15,63.9) 66.597,63.5 75.9,63.5 76.4,63 76.4,59.071 cw(c76.35,59.071) 76.385,59.035 75.915,58.565 cw(c75.879,58.6) 75.879,58.55 63.75,58.55 cw(c63.748,58.6) 63.748,58.55 63.521,58.55 ccw(c63.521,58) 63.132,58.389 62.661,57.918 ccw(c63.05,57.529) 62.5,57.529 62.5,56.99 cw(c62.45,56.99) 62.485,56.955 62.39,56.86 ccw(c62.85,56.4) 62.317,56.771 cw(c62.276,56.8) 62.276,56.75
OUT1 on BOTTOM "BOTTOM57" (solid, pour order 25): 79.321,58.55 cw(c79.321,58.6) 79.285,58.565 78.815,59.035 cw(c78.85,59.071) 78.8,59.071 78.8,62.75 cw(c78.849,62.761) 78.799,62.764 ccw(c78.2,62.8) 78.406,63.363 78.405,63.364 78.404,63.364 78.208,63.435 cw(c78.225,63.482) 78.189,63.447 77.368,64.268 ccw(c77.05,63.95) 77.05,64.4 66.649,64.4 cw(c66.649,64.45) 66.622,64.408 66.539,64.462 cw(c66.566,64.504) 66.531,64.469 66.15,64.85 63.546,64.85 cw(c63.546,64.9) 63.532,64.852 cw(c63.546,64.9) 63.51,64.865 63.04,65.335 cw(c63.075,65.371) 63.03,65.348 cw(c63.075,65.371) 63.025,65.371 63.025,70.454 cw(c63.075,70.454) 63.04,70.49 63.041,70.491 63.509,70.959 63.51,70.96 cw(c63.546,70.925) 63.546,70.975 65.732,70.975 ccw(c66.2,71.35) 66.647,70.95 76.843,70.95 cw(c76.843,70.9) 76.878,70.935 77.552,70.261 cw(c77.518,70.225) 77.565,70.242 77.636,70.046 77.636,70.044 ccw(c78.2,70.25) 78.2,69.65 81.679,69.65 cw(c81.679,69.6) 81.715,69.635 86,65.35 90.5,65.35 91,64.85 91,59.071 cw(c90.95,59.071) 90.985,59.035 90.515,58.565 cw(c90.479,58.6) 90.479,58.55
N665551 on BOTTOM "BOTTOM58" (solid, pour order 26): 45.55,85.15 cw(c45.55,85.2) 45.5,85.2 45.5,86.079 cw(c45.55,86.079) 45.515,86.115 45.55,86.15 45.55,87 cw(c45.6,87) 45.6,87.05 46.2,87.05 cw(c46.2,87) 46.25,87 46.25,86.15 46.285,86.115 cw(c46.25,86.079) 46.3,86.079 46.3,85.2 cw(c46.25,85.2) 46.25,85.15
GND on BOTTOM "BOTTOM39" (solid, pour order 7): 28.05,82 cw(c28.05,82.05) 28,82.05 28,82.25 cw(c28.05,82.25) 28.05,82.3 28.7,82.3 cw(c28.7,82.25) 28.75,82.25 28.75,82.05 cw(c28.7,82.05) 28.7,82
D5V on BOTTOM "BOTTOM59" (solid, pour order 27): 44.121,81.55 cw(c44.121,81.6) 44.085,81.565 43.965,81.685 cw(c44,81.721) 43.95,81.721 43.95,83.879 cw(c44,83.879) 43.965,83.915 44.085,84.035 cw(c44.121,84) 44.121,84.05 46.25,84.05 cw(c46.25,84) 46.3,84 46.3,81.6 cw(c46.25,81.6) 46.25,81.55
GND on BOTTOM "BOTTOM35" (solid, pour order 3): 28.05,55.6 cw(c28.05,55.65) 28,55.65 28,55.85 cw(c28.05,55.85) 28.05,55.9 28.7,55.9 cw(c28.7,55.85) 28.75,55.85 28.75,55.65 cw(c28.7,55.65) 28.7,55.6
GND on BOTTOM "BOTTOM36" (solid, pour order 4): 28.05,46.8 cw(c28.05,46.85) 28,46.85 28,47.05 cw(c28.05,47.05) 28.05,47.1 28.7,47.1 cw(c28.7,47.05) 28.75,47.05 28.75,46.85 cw(c28.7,46.85) 28.7,46.8
GND on BOTTOM "BOTTOM37" (solid, pour order 5): 28.05,64.4 cw(c28.05,64.45) 28,64.45 28,64.65 cw(c28.05,64.65) 28.05,64.7 28.7,64.7 cw(c28.7,64.65) 28.75,64.65 28.75,64.45 cw(c28.7,64.45) 28.7,64.4
GND on BOTTOM "BOTTOM38" (solid, pour order 6): 28.05,73.2 cw(c28.05,73.25) 28,73.25 28,73.45 cw(c28.05,73.45) 28.05,73.5 28.7,73.5 cw(c28.7,73.45) 28.75,73.45 28.75,73.25 cw(c28.7,73.25) 28.7,73.2
SIG639 on BOTTOM "BOTTOM47" (solid, pour order 15): 36.25,70.6 36.25,76.25 cw(c36.3,76.25) 36.3,76.3 38.85,76.3 39.05,76.1 39.05,70.45 cw(c39,70.45) 39,70.4 36.45,70.4
VB on BOTTOM "BOTTOM49" (solid, pour order 17): 45,66.1 cw(c45,66.15) 44.95,66.15 44.95,68.1 44.5,68.55 43.121,68.55 cw(c43.121,68.6) 43.085,68.565 41.265,70.385 cw(c41.3,70.421) 41.25,70.421 41.25,71.85 cw(c41.3,71.85) 41.3,71.9 43.9,71.9 44.475,72.475 44.475,72.775 cw(c44.525,72.775) 44.525,72.825 45.875,72.825 cw(c45.875,72.775) 45.925,72.775 45.925,69.45 46.225,69.15 48.45,69.15 cw(c48.45,69.1) 48.5,69.1 48.5,68.6 cw(c48.45,68.6) 48.45,68.55 46,68.55 45.55,68.1 45.55,66.15 cw(c45.5,66.15) 45.5,66.1
VBAT on BOTTOM "BOTTOM42" (solid, pour order 10): 66.996,79.275 cw(c66.996,79.325) 66.96,79.29 66.515,79.735 cw(c66.55,79.771) 66.5,79.771 66.5,88.579 cw(c66.55,88.579) 66.515,88.615 66.985,89.085 cw(c67.021,89.05) 67.021,89.1 76.029,89.1 cw(c76.029,89.05) 76.065,89.085 76.535,88.615 cw(c76.5,88.579) 76.55,88.579 76.55,79.325 cw(c76.5,79.325) 76.5,79.275
VB on BOTTOM "BOTTOM50" (solid, pour order 18): 66.699,71.85 cw(c66.699,71.9) 66.672,71.858 66.531,71.95 ccw(c66.2,71.45) 65.941,71.991 65.94,71.991 65.759,71.905 cw(c65.737,71.95) 65.737,71.9 62.071,71.9 cw(c62.071,71.95) 62.035,71.915 61.75,72.2 58.021,72.2 cw(c58.021,72.25) 57.985,72.215 57.865,72.335 cw(c57.9,72.371) 57.85,72.371 57.85,72.829 cw(c57.9,72.829) 57.865,72.865 58.55,73.55 58.55,76.029 cw(c58.6,76.029) 58.565,76.065 61.06,78.56 cw(c61.096,78.525) 61.096,78.575 77.775,78.575 cw(c77.775,78.525) 77.825,78.525 77.825,71.9 cw(c77.775,71.9) 77.775,71.85
N622087 on BOTTOM "BOTTOM51" (solid, pour order 19): 36.4,78.3 cw(c36.4,78.35) 36.35,78.35 36.35,87.179 cw(c36.4,87.179) 36.365,87.215 39.085,89.935 cw(c39.121,89.9) 39.121,89.95 58.35,89.95 58.35,87.95 44.15,87.95 42.35,86.15 42.35,78.35 cw(c42.3,78.35) 42.3,78.3
GND on BOTTOM "BOTTOM52" (solid, pour order 20): 86.85,79.95 cw(c86.85,80) 86.8,80 86.8,80.2 cw(c86.85,80.2) 86.85,80.25 87.45,80.25 cw(c87.45,80.2) 87.5,80.2 87.5,80 cw(c87.45,80) 87.45,79.95
GND on BOTTOM "BOTTOM53" (solid, pour order 21): 51.765,74.925 cw(c51.765,74.975) 51.716,74.989 ccw(c51.5,75.05) 51.725,75.05 51.725,75.4 ccw(c51.5,75.4) 51.716,75.461 cw(c51.765,75.475) 51.715,75.475 cw(c51.765,75.475) 51.765,75.525 52.3,75.525 cw(c52.3,75.475) 52.35,75.475 ccw(c52.575,75.475) 52.575,75.25 54.625,75.25 ccw(c54.625,75.475) 54.85,75.475 54.85,76.225 ccw(c54.625,76.225) 54.625,76.45 52.575,76.45 ccw(c52.575,76.225) 52.354,76.266 cw(c52.305,76.275) 52.352,76.259 cw(c52.305,76.275) 52.305,76.225 51.765,76.225 cw(c51.765,76.275) 51.715,76.275 cw(c51.765,76.275) 51.716,76.289 ccw(c51.5,76.35) 51.725,76.35 51.725,76.7 ccw(c51.5,76.7) 51.716,76.761 cw(c51.765,76.775) 51.765,76.825 51.775,76.825 ccw(c51.775,77.175) 52.022,76.927 52.022,76.928 52.63,77.535 cw(c52.666,77.5) 52.666,77.55 54.85,77.55 55.05,77.35 55.05,75.316 cw(c55,75.316) 55.035,75.28 54.695,74.94 cw(c54.659,74.975) 54.659,74.925
N622087 on BOTTOM "BOTTOM54" (solid, pour order 22): 57.8,87.95 cw(c57.8,88) 57.75,88 57.75,89.9 cw(c57.8,89.9) 57.8,89.95 60.529,89.95 cw(c60.529,89.9) 60.565,89.935 60.785,89.715 cw(c60.75,89.679) 60.8,89.679 60.8,88.221 cw(c60.75,88.221) 60.785,88.185 60.565,87.965 cw(c60.529,88) 60.529,87.95
N622087 on BOTTOM "BOTTOM60" (solid, pour order 28): 47,86.25 cw(c47,86.3) 46.95,86.3 46.95,87.75 46.665,88.035 cw(c46.7,88.071) 46.65,88.071 46.65,88.35 cw(c46.7,88.35) 46.7,88.4 47.95,88.4 cw(c47.95,88.35) 48,88.35 48,88.071 cw(c47.95,88.071) 47.985,88.035 47.65,87.7 47.65,86.3 cw(c47.6,86.3) 47.6,86.25

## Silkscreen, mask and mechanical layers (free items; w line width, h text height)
Top Overlay:
  lines w0.2: 43.2,83.45 43.35,83.6 43.35,84.4 ; 45.8,84.4 45.8,84.1 46.25,83.65 ; 52.9,83.1 52.9,83.65 53.45,84.2 53.45,84.45
  lines w0.3: 62.8,95.1 64.5,95.1 ; 63.65,94.25 63.65,95.95 ; 80.9,94.55 82.6,94.55
  text "GND" at 53.9,100.6 h0.43 r90
  text "VEXT" at 43.8,99.5 h0.43 r90
  text "DIAG1" at 46.3,99.5 h0.43 r90
  text "DIAG2" at 48.7,99.5 h0.43 r90
  text "MODE" at 51.3,99.5 h0.43 r90
  text "VBAT" at 59.5,99.3 h0.71
  text "Ext.MCU" at 32.2,92.8 h0.61
  text "Op." at 28.372,89.878 h0.8 r270
  text "Normal" at 29.642,89.865 h0.8 r270
  text "Sleep" at 24.4,89.5 h0.8 r270
  text "5V" at 89.325,87.425 h0.61
  text "GND" at 88.5,85.025 h0.61
  text "IN3" at 51.3,82.792 h0.43 r90
  text "IN2" at 48.75,82.692 h0.43 r90
  text "RESET" at 86.45,82.475 h0.61
  text "IN1" at 47,81.923 h0.43 r90
  text "IN4" at 53.15,81.092 h0.43 r90
  text "nSLEEP" at 33.85,81.075 h0.9
  text "nSLEEP" at 42.85,80.525 h0.43 r90
  text "SE" at 89.025,80.025 h0.61
  text "D5V" at 50.1,79.475 h0.71
  text "L" at 22,77.9 h0.8
  text "H" at 32.2,77.875 h0.8
  text "WS" at 89.052,77.325 h0.61
  text "CK" at 89.025,74.025 h0.61
  text "IN1" at 33.697,71.625 h0.9
  text "L" at 22,69.1 h0.8
  text "H" at 32.2,69.075 h0.8
  text "MOTOR" at 84.974,66.675 h0.8
  text "IN2" at 33.718,62.825 h0.9
  text "1" at 80.48,61.525 h0.71
  text "L" at 22,60.3 h0.8
  text "H" at 32.2,60.275 h0.8
  text "TB9103FTG" at 48.662,55.8 h1.3
  text "IN3" at 33.718,54.025 h0.9
  text "2" at 81.3,54 h0.71
  text "L" at 22,51.5 h0.8
  text "H" at 32.2,51.475 h0.8
  text "DIAG1" at 50.147,49.875 h0.71
  text "GND" at 79.35,46.375 h0.71
  text "IN4" at 33.718,45.475 h0.9
  text "DIAG2" at 50.168,45.175 h0.71
  text "L" at 22,42.7 h0.8
  text "H" at 32.2,42.675 h0.8
  text "MODE" at 40.874,41.675 h0.8
  text "0.6V" at 60.35,41.5 h0.61
  text "0.3V" at 55.5,41.4 h0.61
  text "H" at 45.3,40.175 h0.61
  text "Half-" at 32.182,37.922 h0.8
  text "Disable" at 48.277,37.275 h0.61
  text "0.9V" at 64.85,37.1 h0.61
  text "Bridge" at 33.68,36.589 h0.8
  text "RD245" at 74.7,35.7 h1.7
  text "H-Bridge" at 32.3,32.6 h0.8
  text "VDS" at 51.3,31.225 h0.8
  text "L" at 45.3,29.65 h0.61
Bottom Overlay:
  lines w0.2: 31.7,89.3 50.3,89.3 ; 31.7,91.2 50.3,91.2 ; 31.7,93.1 50.3,93.1 ; 31.7,95 50.3,95 ; 42.7,87.4 42.7,98 ; 43.3,78.7 43.3,77.4 43.5,77.2 ; 46.5,87.4 46.5,89.1 46.5,98 ; 46.549,87.4 50.3,87.4 50.3,98 31.7,98 31.7,87.4 46.55,87.4 ; 46.9,65 46.9,65.2 47.1,65.4 ; 49.5,66.25 50.2,66.25 ; 50.9,89.3 67.6,89.3 ; 50.9,91.2 67.6,91.2 ; 50.9,93.1 67.6,93.1 ; 50.9,95 67.6,95 ; 61.4,87.4 61.4,96.95 ; 64.5,87.4 64.5,96.95 ; 88.5,75.4 89.1,76 ; 50.9,87.4 67.6,87.4 67.6,96.95 50.9,96.95 50.9,87.4
  text "Half-Bridge Mode" at 48.5,100.2 h0.8
  text "H-Bridge Mode" at 65.245,99.275 h0.8
  text "(Normal Op.)" at 48.9,98.7 h0.8
  text "(Normal Op.)" at 64.298,97.625 h0.8
  text "IN2" at 45.7,96.65 h0.8
  text "IN1" at 49.5,96.65 h0.8
  text "Output State" at 41.466,96.125 h0.8
  text "Output" at 61.016,95.675 h0.8
  text "State" at 55.345,95.525 h0.8
  text "IN2" at 64.05,95.5 h0.8
  text "IN1" at 67,95.5 h0.8
  text "/IN4" at 46.1,95.35 h0.8
  text "/IN3" at 49.9,95.35 h0.8
  text "Hi-Z" at 42.2,93.55 h0.8
  text "L" at 44.8,93.55 h0.8
  text "L" at 48.6,93.55 h0.8
  text "L" at 63.3,93.55 h0.8
  text "L" at 66.25,93.55 h0.8
  text "Hi-Z" at 57.898,93.525 h0.8
  text "L" at 63.3,91.85 h0.8
  text "High-Side ON" at 42.2,91.8 h0.8
  text "L" at 44.8,91.65 h0.8
  text "H" at 48.7,91.65 h0.8
  text "H" at 66.25,91.65 h0.8
  text "Forward" at 57.9,91.625 h0.8
  text "H" at 44.8,89.75 h0.8
  text "L" at 48.7,89.75 h0.8
  text "H" at 63.3,89.75 h0.8
  text "L" at 66.25,89.75 h0.8
  text "Low-Side ON" at 42.073,89.625 h0.8
  text "Reverse" at 57.9,89.625 h0.8
  text "Brake" at 57.9,87.875 h0.8
  text "Hi-Z" at 42.2,87.85 h0.8
  text "H" at 44.8,87.85 h0.8
  text "H" at 48.7,87.85 h0.8
  text "H" at 63.3,87.85 h0.8
  text "H" at 66.25,87.85 h0.8
OUTLINE:
  lines w0.001: 19.95,65.5 ccw(c20,65.5) 20.05,65.5 ; 19.95,65.5 cw(c20,65.5) 20.05,65.5 ; 19.95,65.5 19.95,101 cw(c22,101) 22,103.05 23.5,103.05 ccw(c23.5,103.5) 23.95,103.5 ; 19.95,65.5 19.95,30 ccw(c22,30) 22,27.95 23.5,27.95 cw(c23.5,27.5) 23.95,27.5 ; 20.05,65.5 20.05,101 cw(c22,101) 22,102.95 23.5,102.95 ccw(c23.5,103.5) 24.05,103.5 ; 20.05,65.5 20.05,30 ccw(c22,30) 22,28.05 23.5,28.05 cw(c23.5,27.5) 24.05,27.5 ; 23.95,27.5 cw(c23.5,27.5) 23.5,27.05 20,27.05 ccw(c20,27) 19.95,27 19.95,20 ccw(c20,20) 20,19.95 95,19.95 ccw(c95,20) 95.05,20 95.05,27 ccw(c95,27) 95,27.05 91.5,27.05 cw(c91.5,27.5) 91.05,27.5 ; 23.95,27.5 cw(c24,27.5) 24.05,27.5 ; 23.95,27.5 ccw(c24,27.5) 24.05,27.5 ; 23.95,103.5 cw(c24,103.5) 24.05,103.5 ; 23.95,103.5 ccw(c23.5,103.5) 23.5,103.95 20,103.95 cw(c20,104) 19.95,104 19.95,111 cw(c20,111) 20,111.05 95,111.05 cw(c95,111) 95.05,111 95.05,104 cw(c95,104) 95,103.95 91.5,103.95 ccw(c91.5,103.5) 91.05,103.5 ; 23.95,103.5 ccw(c24,103.5) 24.05,103.5 ; 24.05,27.5 cw(c23.5,27.5) 23.5,26.95 20.05,26.95 20.05,20.05 94.95,20.05 94.95,26.95 91.5,26.95 cw(c91.5,27.5) 90.95,27.5 ; 24.05,103.5 ccw(c23.5,103.5) 23.5,104.05 20.05,104.05 20.05,110.95 94.95,110.95 94.95,104.05 91.5,104.05 ccw(c91.5,103.5) 90.95,103.5 ; 25.95,27.5 cw(c26.5,27.5) 26.5,28.05 88.5,28.05 cw(c88.5,27.5) 89.05,27.5 ; 25.95,27.5 ccw(c26,27.5) 26.05,27.5 ; 25.95,27.5 cw(c26,27.5) 26.05,27.5 ; 25.95,27.5 ccw(c26.5,27.5) 26.5,26.95 87.7,26.95 ; 25.95,103.5 cw(c26.5,103.5) 26.5,104.05 27.3,104.05 ; 25.95,103.5 ccw(c26,103.5) 26.05,103.5 ; 25.95,103.5 cw(c26,103.5) 26.05,103.5 ; 25.95,103.5 ccw(c26.5,103.5) 26.5,102.95 88.5,102.95 ccw(c88.5,103.5) 89.05,103.5 ; 26.05,27.5 cw(c26.5,27.5) 26.5,27.95 88.5,27.95 cw(c88.5,27.5) 88.95,27.5 ; 26.05,27.5 ccw(c26.5,27.5) 26.5,27.05 87.7,27.05 ; 26.05,103.5 cw(c26.5,103.5) 26.5,103.95 27.3,103.95 ; 26.05,103.5 ccw(c26.5,103.5) 26.5,103.05 88.5,103.05 ccw(c88.5,103.5) 88.95,103.5 ; 27.3,103.95 ccw(c27.3,104) 27.3,104.05 ; 27.3,103.95 cw(c27.3,104) 27.3,104.05 ; 27.3,103.95 88.5,103.95 cw(c88.5,103.5) 88.95,103.5 ; 27.3,104.05 88.5,104.05 cw(c88.5,103.5) 89.05,103.5 ; 87.7,26.95 cw(c87.7,27) 87.7,27.05 ; 87.7,26.95 ccw(c87.7,27) 87.7,27.05 ; 87.7,26.95 88.5,26.95 ccw(c88.5,27.5) 89.05,27.5 ; 87.7,27.05 88.5,27.05 ccw(c88.5,27.5) 88.95,27.5 ; 88.95,27.5 cw(c89,27.5) 89.05,27.5 ; 88.95,27.5 ccw(c89,27.5) 89.05,27.5 ; 88.95,103.5 cw(c89,103.5) 89.05,103.5 ; 88.95,103.5 ccw(c89,103.5) 89.05,103.5 ; 90.95,27.5 cw(c91.5,27.5) 91.5,28.05 93,28.05 ccw(c93,30) 94.95,30 94.95,101 ccw(c93,101) 93,102.95 91.5,102.95 cw(c91.5,103.5) 90.95,103.5 ; 90.95,27.5 ccw(c91,27.5) 91.05,27.5 ; 90.95,27.5 cw(c91,27.5) 91.05,27.5 ; 90.95,103.5 ccw(c91,103.5) 91.05,103.5 ; 90.95,103.5 cw(c91,103.5) 91.05,103.5 ; 91.05,27.5 cw(c91.5,27.5) 91.5,27.95 93,27.95 ccw(c93,30) 95.05,30 95.05,101 ccw(c93,101) 93,103.05 91.5,103.05 cw(c91.5,103.5) 91.05,103.5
